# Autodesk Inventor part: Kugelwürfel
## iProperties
Shininess: 64.0
Length Units: 11269
Angle Units: 11279
Time Units: 11290
Mass Units: 11283
Length Display Precision: 3
Angle Display Precision: 2
Compacted: True
Part Number: Kugelwürfel
Document SubType Name: Modeling
Created: 2004-10
Material: Standard
Cost Center: 0 kg
Designer: thomas
Manufacturer: Standard
Standards Organization: Custom
Density: 0.0
Volumn: 0.0
Area: 0.0
PropertySet Name: Model Information
Control State: 0
Master: False
Checked Out: False
SaveDate: 2004-10-27
SaveTime: 19:47
TotalMass: 0 kg
Author: thomas
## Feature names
1. Extrusion1
2. Rundung1 [Fillet]
3. Rundung2 [Fillet]
